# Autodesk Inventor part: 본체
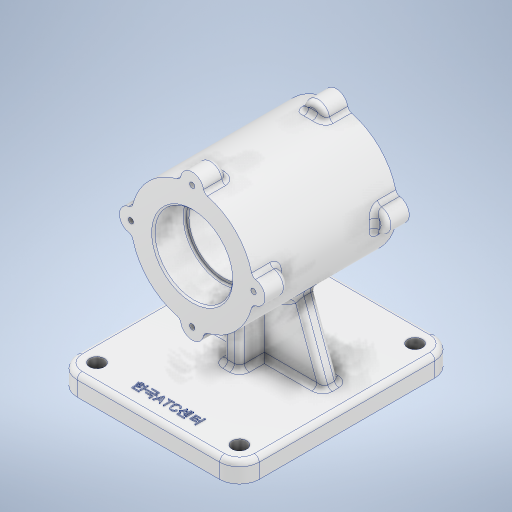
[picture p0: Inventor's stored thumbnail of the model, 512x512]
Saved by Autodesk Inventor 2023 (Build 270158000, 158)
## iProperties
Created: 2023-08
Part Number: 본체
Material: 알루미늄 6061
Document SubType Name: Modeling
Designer: asung
Density: 2.7 g/cm^3
Appearance: 알루미늄 - 평지
Author: asung
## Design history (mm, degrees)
sketch "스케치1"
  geometry: L1 (43, 65)-(-43, 65); L2 (-55, 53)-(-55, -53); L3 (-43, -65)-(43, -65); L4 (55, -53)-(55, 53); L5 (55, 65)-(-55, -65); L6 (-55, 65)-(55, -65); C1 r 4.5 at (43, -53); C2 r 4.5 at (-43, -53); C3 r 4.5 at (-43, 53); C4 r 4.5 at (43, 53); A1 r 12 centre (43, 53) between (55, 53) and (43, 65); A2 r 12 centre (43, -53) between (43, -65) and (55, -53); A3 r 12 centre (-43, -53) between (-55, -53) and (-43, -65); A4 r 12 centre (-43, 53) between (-43, 65) and (-55, 53); 1 further point
  constraints: 12 end point, 8 centre point, 8 point on circle, 8 point on line, 8 tangent, 4 coincident, 3 equal radius, 2 midpoint, 2 parallel, 1 horizontal, 1 perpendicular
  dimensions: "d0" = 110 distance of L6.end L5.end; "d1" = 130 distance of L5.end L6.start; "d2" = 12 radius of A1; "d3" = 9 diameter of C1; "d4" = 9 diameter of C2; "d5" = 9 diameter of C3; "d6" = 9 diameter of C4
extrude "돌출1" new body sketch "스케치1" distance "d7" = 12; taper "d8" = 0 deg
fillet "모깎기1" dims "d9" = 3
node "작업 평면1"
node "작업 평면2"
sketch "스케치3"
  geometry: L1 (-9, 12)-(95, 12) reference; L2 (98, 9)-(98, 0) reference; L3 (98, 0)-(-12, 0) reference; L4 (-12, 0)-(-12, 9) reference; L5 (43, 0)-(43, 82); C1 r 37 at (43, 82); A1 r 3 centre (-9, 9) between (-9, 12) and (-12, 9) reference; A2 r 3 centre (95, 9) between (98, 9) and (95, 12) reference
  constraints: 2 end point, 1 centre point, 1 coincident, 1 vertical
  dimensions: "d12" = 82 distance of L5.start L5.end; "d13" = 74 diameter of C1
extrude "돌출2" join sketch "스케치3" stored distance "d14" = 87; taper "d15" = 0 deg
sketch "스케치4"
  geometry: C1 r 7 at (0, 37); 4 further points
  constraints: 1 centre point, 2 other
  dimensions: "d16" = 14 diameter of C1
extrude "돌출3" join sketch "스케치4" distance "d17" = 14; taper "d18" = 0 deg
sketch "스케치5"
  geometry: A1 r 7 centre (43, 119) between (49.969, 118.338) and (36.031, 118.338) reference; 2 further points
  constraints: 1 coincident
hole "구멍1" sketch "스케치5" at (43, 119) diameter "d19" = 3.242; stored, may be unused: countersink angle "d23" = 90 deg, drill point angle "d25" = 118 deg; dims "d20" = 8, "d21" = 4, "d22" = 2, "d24" = 10
fillet "모깎기2" dims "d26" = 3
fillet "모깎기3" dims "d27" = 3
node "작업 평면3"
sketch "스케치6"
  geometry: L1 (12, 62)-(12, -62) reference; L2 (9, -65)-(0, -65) reference; L3 (0, -65)-(0, 65) reference; L4 (0, 65)-(9, 65) reference; L5 (119, 27.526)-(120.621, 28.5) reference; L6 (120.621, 28.5)-(120.621, 38.5) reference; L7 (120.621, 38.5)-(126, 38.5) reference; L8 (126, 38.5)-(126, 27.5) reference; L9 (123, 24.5)-(122, 24.5) reference; L10 (119, 21.5)-(119, -31.5) reference; L11 (122, -34.5)-(123, -34.5) reference; L12 (126, -37.5)-(126, -48.5) reference; L13 (126, -48.5)-(120.621, -48.5) reference; L14 (120.621, -48.5)-(120.621, -38.5) reference; L15 (120.621, -38.5)-(119, -37.526) reference; L16 (119, -37.526)-(117.379, -38.5) reference; L17 (117.379, -38.5)-(117.379, -48.5) reference; L18 (117.379, -48.5)-(46.621, -48.5) reference; L19 (46.621, -48.5)-(46.621, -38.5) reference; L20 (46.621, -38.5)-(45, -37.526) reference; L21 (45, -37.526)-(43.379, -38.5) reference; L22 (43.379, -38.5)-(43.379, -48.5) reference; L23 (43.379, -48.5)-(38, -48.5) reference; L24 (38, -48.5)-(38, -37.5) reference; L25 (41, -34.5)-(42, -34.5) reference; L26 (45, -31.5)-(45, 21.5) reference; L27 (42, 24.5)-(41, 24.5) reference; L28 (38, 27.5)-(38, 38.5) reference; L29 (38, 38.5)-(43.379, 38.5) reference; L30 (43.379, 38.5)-(43.379, 28.5) reference; L31 (43.379, 28.5)-(45, 27.526) reference; L32 (45, 27.526)-(46.621, 28.5) reference; L33 (46.621, 28.5)-(46.621, 38.5) reference; L34 (46.621, 38.5)-(117.379, 38.5) reference; L35 (117.379, 38.5)-(117.379, 28.5) reference; L36 (117.379, 28.5)-(119, 27.526) reference; L37 (88.889, 38.5)-(75.111, 38.5) reference; L38 (82, 38.5)-(82, -48.5); L39 (83.621, -48.5)-(80.379, -48.5) reference; L40 (82, 38.5)-(105.5, 38.5); L41 (117.863, 38.5)-(91.104, 38.5) reference; L42 (105.5, 38.5)-(105.5, 20.5); L43 (104.5, 19.5)-(103, 19.5); L44 (82, -48.5)-(105.5, -48.5); L45 (91.104, -48.5)-(117.863, -48.5) reference; L46 (105.5, -48.5)-(105.5, -30.5); L47 (104.5, -29.5)-(103, -29.5); L48 (103, -29.5)-(103, 19.5); A1 r 3 centre (9, 62) between (12, 62) and (9, 65) reference; A2 r 3 centre (9, -62) between (9, -65) and (12, -62) reference; A3 r 3 centre (123, 27.5) between (123, 24.5) and (126, 27.5) reference; A4 r 3 centre (122, 21.5) between (122, 24.5) and (119, 21.5) reference; A5 r 3 centre (122, -31.5) between (119, -31.5) and (122, -34.5) reference; A6 r 3 centre (123, -37.5) between (126, -37.5) and (123, -34.5) reference; A7 r 3 centre (41, -37.5) between (41, -34.5) and (38, -37.5) reference; A8 r 3 centre (42, -31.5) between (42, -34.5) and (45, -31.5) reference; A9 r 3 centre (42, 21.5) between (45, 21.5) and (42, 24.5) reference; A10 r 3 centre (41, 27.5) between (38, 27.5) and (41, 24.5) reference; A11 r 1 centre (104.5, 20.5) between (104.5, 19.5) and (105.5, 20.5); A12 r 1 centre (104.5, -30.5) between (105.5, -30.5) and (104.5, -29.5); 7 further points
  constraints: 16 end point, 6 point on line, 4 point on circle, 4 tangent, 3 perpendicular, 2 centre point, 2 midpoint, 1 equal radius, 1 vertical
  dimensions: "d31" = 23.5 distance of L38.start L40.end; "d32" = 19 distance of L40.end point (105.5, 19.5); "d33" = 2.5 distance of point (105.5, 19.5) L43.end; "d34" = 23.5 distance of L38.end L44.end; "d35" = 19 distance of L44.end point (105.5, -29.5); "d36" = 2.5 distance of point (105.5, -29.5) L47.end; "d37" = 1 radius of A11
revolve "회전1" sketch "스케치6" stored, may be unused: angle "d38" = 90 deg
chamfer "모따기1" distance "d39" = 1; stored, may be unused: second distance "d40" = 2, angle "d41" = 45 deg
sketch "스케치7"
  geometry: L1 (-43, -65)-(43, -65) reference; L2 (-55, 53)-(-55, -53) reference; L3 (43, 65)-(-43, 65) reference; L4 (55, -53)-(55, 53) reference; L5 (0, -65)-(0, 5); L6 (-5, -15)-(5, -15); L7 (5, -15)-(5, 25); L8 (5, 25)-(-5, 25); L9 (-5, 25)-(-5, -15); L10 (-5, -15)-(5, 25); L11 (5, -15)-(-5, 25); C1 r 4.5 at (-43, -53) reference; C2 r 4.5 at (43, -53) reference; C3 r 4.5 at (43, 53) reference; C4 r 4.5 at (-43, 53) reference; A1 r 12 centre (43, -53) between (43, -65) and (55, -53) reference; A2 r 12 centre (-43, -53) between (-55, -53) and (-43, -65) reference; A3 r 12 centre (-43, 53) between (-43, 65) and (-55, 53) reference; A4 r 12 centre (43, 53) between (55, 53) and (43, 65) reference; 1 further point
  constraints: 14 end point, 3 midpoint, 2 parallel, 1 horizontal, 1 perpendicular, 1 vertical
  dimensions: "d42" = 70 distance of L5.start L5.end; "d43" = 10 distance of L8.end L7.end; "d44" = 40 distance of L7.end L6.end
extrude "돌출4" join sketch "스케치7" stored distance "d45" = 14; taper "d46" = 0 deg
node "작업 평면4"
sketch "스케치8"
  geometry: L1 (-9, 12)-(38, 12) reference; L2 (38, 12)-(38, 45.339) reference; L3 (48, 45.339)-(48, 12) reference; L4 (48, 12)-(95, 12) reference; L5 (98, 9)-(98, 0) reference; L6 (98, 0)-(-12, 0) reference; L7 (-12, 0)-(-12, 9) reference; L8 (98, 12)-(84, 12); L9 (81.5, 12)-(90.5, 12) reference; L10 (84, 12)-(66.128, 61.104); L11 (-12, 12)-(2, 12); L12 (2, 12)-(20.401, 62.557); L13 (20.401, 62.557)-(38, 48.571); L14 (38, 12)-(38, 45.339) reference; L15 (38, 48.571)-(38, 12); L16 (66.128, 61.104)-(48, 50.911); L17 (48, 12)-(48, 45.339) reference; L18 (48, 50.911)-(48, 12); C1 r 21 at (43, 82) reference; A1 r 3 centre (-9, 9) between (-9, 12) and (-12, 9) reference; A2 r 37 centre (43, 82) between (48, 45.339) and (38, 45.339) reference; A3 r 3 centre (95, 9) between (98, 9) and (95, 12) reference; 4 further points
  constraints: 16 end point, 2 collinear, 2 point on line
  dimensions: "d47" = 14 distance of L8.start L8.end; "d48" = 110 deg angle of L4 L10; "d49" = 14 distance of L11.start L11.end; "d50" = 110 deg angle of L1 L12
extrude "돌출5" join sketch "스케치8" stored distance "d51" = 10; taper "d52" = 0 deg
fillet "모깎기4" dims "d53" = 3
fillet "모깎기5" dims "d54" = 3
fillet "모깎기6" dims "d55" = 3
sketch "스케치9"
  geometry: L1 (43, 65)-(-43, 65) reference; 2 further points
  constraints: 1 other
  dimensions: "d57" = 118 distance from line of point (0, -53) L1
feature "엠보싱1" sketch "스케치9" dims "d0" = 110, "d1" = 130, "d2" = 12, "d3" = 9, "d4" = 9, "d5" = 9, "d6" = 9, "d58" = 0.5, "d59" = 0
node "솔리드1"
pattern_circular "원형 패턴1" dims "d29" = 360 deg
mirror "미러1"
node "투영된 루프1"
node "절단 모서리 투영2"
node "절단 모서리 투영3"
node "절단 모서리 투영4"
feature "A9D066F2-1C7D-4E18-AEED-F7BC21143FA4" dims "d19" = 3.242, "d20" = 8, "d21" = 4, "d22" = 2, "d23" = 90 deg, "d24" = 10, "d25" = 118 deg
